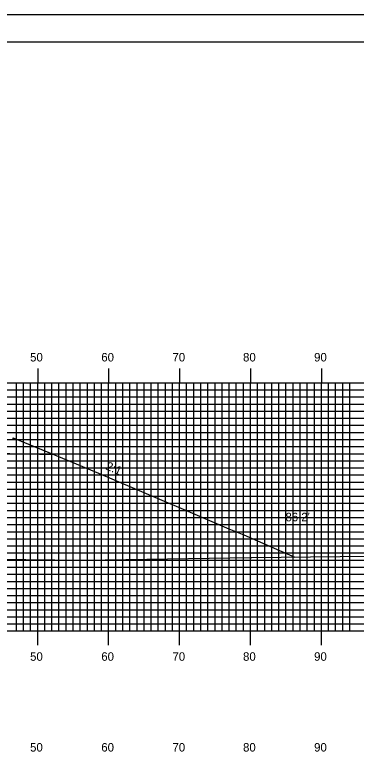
# Model space of a CAD drawing. Extents: x 1756282 to 1756625, y 442591 to 442811.
# Drawn here: x 1756494.3 to 1756542.5, y 442706.2 to 442810.5 of the extents above; entities that cross this region are included whole.
import ezdxf

# ---------------------------------------------------------------- set-up
doc = ezdxf.new("R2010")
doc.units = 0
for name, color, linetype in [('ANNOTATION', 7, 'Continuous'), ('BORDER', 7, 'Continuous'), ('D_Roadway_Centerline', 7, 'Continuous'), ('D_Roadway_SlopeLines', 7, 'Continuous'), ('D_Roadway_SubGrade', 7, 'Continuous'), ('D_Text_Standard', 7, 'Continuous'), ('H_V ANNOTATION', 7, 'Continuous'), ('MAJOR', 7, 'Continuous'), ('MINOR', 7, 'Continuous'), ('PLOT BOUNDARY', 7, 'Continuous'), ('S_Roadway_Centerline', 7, 'Continuous')]:
    doc.layers.add(name, color=color, linetype=linetype)

msp = doc.modelspace()

# ---------------------------------------------------------------- linework, layer by layer
at = {"layer": 'BORDER'}
msp.add_lwpolyline([(1756297.97, 442596.67), (1756617.97, 442596.67), (1756617.97, 442806.67), (1756297.97, 442806.67)], close=True, dxfattribs=at)
at = {"layer": 'D_Roadway_Centerline'}
msp.add_lwpolyline([(1756494.12, 442750.91), (1756495.24, 442750.44), (1756499.94, 442748.5), (1756503.58, 442746.98), (1756503.87, 442746.86), (1756506.16, 442745.9), (1756508.36, 442744.96), (1756515.09, 442742.13), (1756517.09, 442741.27), (1756519.07, 442740.44), (1756524.52, 442738.09), (1756526.61, 442737.21), (1756531.64, 442735.03), (1756531.99, 442734.88), (1756533.8, 442734.1)], dxfattribs=at)
at = {"layer": 'D_Roadway_SlopeLines'}
msp.add_line((1756499.94, 442748.5), (1756499.94, 442748.5), dxfattribs=at)
at = {"layer": 'D_Roadway_SubGrade'}
msp.add_lwpolyline([(1756483.08, 442750.71), (1756483.08, 442751.12), (1756494.12, 442750.66), (1756494.12, 442750.91), (1756499.94, 442748.5), (1756483.08, 442748.87)], close=True, dxfattribs=at)
at = {"layer": 'MAJOR'}
for p, q in [((1756497.57, 442760.67), (1756497.57, 442758.67)), ((1756507.57, 442760.67), (1756507.57, 442758.67)), ((1756517.57, 442760.67), (1756517.57, 442758.67)), ((1756527.57, 442760.67), (1756527.57, 442758.67)), ((1756537.57, 442760.67), (1756537.57, 442758.67)), ((1756307.57, 442758.67), (1756587.57, 442758.67)), ((1756307.57, 442758.67), (1756587.57, 442758.67)), ((1756497.57, 442723.67), (1756497.57, 442758.67)), ((1756507.57, 442723.67), (1756507.57, 442758.67)), ((1756517.57, 442723.67), (1756517.57, 442758.67)), ((1756527.57, 442723.67), (1756527.57, 442758.67)), ((1756537.57, 442723.67), (1756537.57, 442758.67)), ((1756307.57, 442753.67), (1756587.57, 442753.67)), ((1756307.57, 442748.67), (1756587.57, 442748.67)), ((1756307.57, 442743.67), (1756587.57, 442743.67)), ((1756307.57, 442738.67), (1756587.57, 442738.67)), ((1756307.57, 442733.67), (1756587.57, 442733.67)), ((1756307.57, 442728.67), (1756587.57, 442728.67)), ((1756307.57, 442723.67), (1756587.57, 442723.67)), ((1756307.57, 442723.67), (1756587.57, 442723.67)), ((1756497.57, 442721.66), (1756497.57, 442723.67)), ((1756507.57, 442721.66), (1756507.57, 442723.67)), ((1756517.57, 442721.66), (1756517.57, 442723.67)), ((1756527.57, 442721.66), (1756527.57, 442723.67)), ((1756537.57, 442721.66), (1756537.57, 442723.67))]:
    msp.add_line(p, q, dxfattribs=at)
at = {"layer": 'MINOR'}
for p, q in [((1756494.57, 442723.67), (1756494.57, 442758.67)), ((1756495.57, 442723.67), (1756495.57, 442758.67)), ((1756496.57, 442723.67), (1756496.57, 442758.67)), ((1756498.57, 442723.67), (1756498.57, 442758.67)), ((1756499.57, 442723.67), (1756499.57, 442758.67)), ((1756500.57, 442723.67), (1756500.57, 442758.67)), ((1756501.57, 442723.67), (1756501.57, 442758.67)), ((1756502.57, 442723.67), (1756502.57, 442758.67)), ((1756503.57, 442723.67), (1756503.57, 442758.67)), ((1756504.57, 442723.67), (1756504.57, 442758.67)), ((1756505.57, 442723.67), (1756505.57, 442758.67)), ((1756506.57, 442723.67), (1756506.57, 442758.67)), ((1756508.57, 442723.67), (1756508.57, 442758.67)), ((1756509.57, 442723.67), (1756509.57, 442758.67)), ((1756510.57, 442723.67), (1756510.57, 442758.67)), ((1756511.57, 442723.67), (1756511.57, 442758.67)), ((1756512.57, 442723.67), (1756512.57, 442758.67)), ((1756513.57, 442723.67), (1756513.57, 442758.67)), ((1756514.57, 442723.67), (1756514.57, 442758.67)), ((1756515.57, 442723.67), (1756515.57, 442758.67)), ((1756516.57, 442723.67), (1756516.57, 442758.67)), ((1756518.57, 442723.67), (1756518.57, 442758.67)), ((1756519.57, 442723.67), (1756519.57, 442758.67)), ((1756520.57, 442723.67), (1756520.57, 442758.67)), ((1756521.57, 442723.67), (1756521.57, 442758.67)), ((1756522.57, 442723.67), (1756522.57, 442758.67)), ((1756523.57, 442723.67), (1756523.57, 442758.67)), ((1756524.57, 442723.67), (1756524.57, 442758.67)), ((1756525.57, 442723.67), (1756525.57, 442758.67)), ((1756526.57, 442723.67), (1756526.57, 442758.67)), ((1756528.57, 442723.67), (1756528.57, 442758.67)), ((1756529.57, 442723.67), (1756529.57, 442758.67)), ((1756530.57, 442723.67), (1756530.57, 442758.67)), ((1756531.57, 442723.67), (1756531.57, 442758.67)), ((1756532.57, 442723.67), (1756532.57, 442758.67)), ((1756533.57, 442723.67), (1756533.57, 442758.67)), ((1756534.57, 442723.67), (1756534.57, 442758.67)), ((1756535.57, 442723.67), (1756535.57, 442758.67)), ((1756536.57, 442723.67), (1756536.57, 442758.67)), ((1756538.57, 442723.67), (1756538.57, 442758.67)), ((1756539.57, 442723.67), (1756539.57, 442758.67)), ((1756540.57, 442723.67), (1756540.57, 442758.67)), ((1756541.57, 442723.67), (1756541.57, 442758.67)), ((1756307.57, 442757.67), (1756587.57, 442757.67)), ((1756307.57, 442756.67), (1756587.57, 442756.67)), ((1756307.57, 442755.67), (1756587.57, 442755.67)), ((1756307.57, 442754.67), (1756587.57, 442754.67)), ((1756307.57, 442752.67), (1756587.57, 442752.67)), ((1756307.57, 442751.67), (1756587.57, 442751.67)), ((1756307.57, 442750.67), (1756587.57, 442750.67)), ((1756307.57, 442749.67), (1756587.57, 442749.67)), ((1756307.57, 442747.67), (1756587.57, 442747.67)), ((1756307.57, 442746.67), (1756587.57, 442746.67)), ((1756307.57, 442745.67), (1756587.57, 442745.67)), ((1756307.57, 442744.67), (1756587.57, 442744.67)), ((1756307.57, 442742.67), (1756587.57, 442742.67)), ((1756307.57, 442741.67), (1756587.57, 442741.67)), ((1756307.57, 442740.67), (1756587.57, 442740.67)), ((1756307.57, 442739.67), (1756587.57, 442739.67)), ((1756307.57, 442737.67), (1756587.57, 442737.67)), ((1756307.57, 442736.67), (1756587.57, 442736.67)), ((1756307.57, 442735.67), (1756587.57, 442735.67)), ((1756307.57, 442734.67), (1756587.57, 442734.67)), ((1756307.57, 442732.67), (1756587.57, 442732.67)), ((1756307.57, 442731.67), (1756587.57, 442731.67)), ((1756307.57, 442730.67), (1756587.57, 442730.67)), ((1756307.57, 442729.67), (1756587.57, 442729.67)), ((1756307.57, 442727.67), (1756587.57, 442727.67)), ((1756307.57, 442726.67), (1756587.57, 442726.67)), ((1756307.57, 442725.67), (1756587.57, 442725.67)), ((1756307.57, 442724.67), (1756587.57, 442724.67))]:
    msp.add_line(p, q, dxfattribs=at)
at = {"layer": 'PLOT BOUNDARY'}
msp.add_lwpolyline([(1756281.78, 442590.55), (1756621.78, 442590.55), (1756621.78, 442810.55), (1756281.78, 442810.55)], close=True, dxfattribs=at)
at = {"layer": 'S_Roadway_Centerline'}
msp.add_lwpolyline([(1756392.32, 442733.26), (1756405.53, 442733.01), (1756413.22, 442733.07), (1756424.6, 442732.44), (1756425.66, 442732.44), (1756426.59, 442732.45), (1756432.29, 442733.09), (1756434.26, 442733.16), (1756442.01, 442733.34), (1756447.68, 442733.55), (1756453.5, 442733.61), (1756470.52, 442733.86), (1756482.57, 442733.74), (1756495.91, 442733.76), (1756504.14, 442733.66), (1756527.63, 442734.03), (1756527.67, 442734.03), (1756527.69, 442734.03), (1756527.75, 442734.03), (1756548.47, 442734.25)], dxfattribs=at)

# ---------------------------------------------------------------- texts
at = {"layer": 'ANNOTATION'}
msp.add_text('2:1', height=1.2, rotation=336.8621, dxfattribs=at).set_placement((1756507.06, 442746.49))
at = {"layer": 'D_Text_Standard'}
msp.add_text("86.2'", height=1.2, dxfattribs=at).set_placement((1756532.5, 442739.14))
at = {"layer": 'H_V ANNOTATION'}
for s, p in [('50', (1756496.5, 442761.67)), ('60', (1756506.54, 442761.67)), ('70', (1756516.57, 442761.67)), ('80', (1756526.52, 442761.67)), ('90', (1756536.54, 442761.67)), ('50', (1756496.5, 442719.47)), ('60', (1756506.54, 442719.47)), ('70', (1756516.57, 442719.47)), ('80', (1756526.52, 442719.47)), ('90', (1756536.54, 442719.47)), ('50', (1756496.5, 442706.67)), ('60', (1756506.54, 442706.67)), ('70', (1756516.57, 442706.67)), ('80', (1756526.52, 442706.67)), ('90', (1756536.54, 442706.67))]:
    msp.add_text(s, height=1.2, dxfattribs=at).set_placement(p)

doc.saveas('drawing.dxf')
